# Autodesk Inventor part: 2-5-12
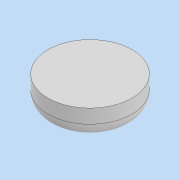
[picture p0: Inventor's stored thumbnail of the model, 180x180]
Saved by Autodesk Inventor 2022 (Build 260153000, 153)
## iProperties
Created: 2021-07
Part Number: 2-5-12
Material: 一般
Document SubType Name: Modeling
Designer: DesignLab
Density: 1 g/cm^3
Appearance: 既定
Author: DesignLab
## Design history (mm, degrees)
sketch "スケッチ1"
  geometry: C1 r 15 at (0, 0); 1 further point
  constraints: 1 centre point, 1 coincident
  dimensions: "d0" = 30 diameter of C1
extrude "押し出し1" new body sketch "スケッチ1" distance "d1" = 10; taper "d2" = 0 deg
fillet "フィレット1" dims "d3" = 5
node "ソリッド1"
